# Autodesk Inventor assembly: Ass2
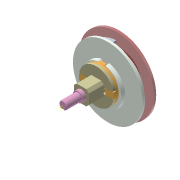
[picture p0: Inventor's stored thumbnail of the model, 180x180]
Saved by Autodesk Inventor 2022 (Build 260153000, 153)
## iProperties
Created: 2013-05
Part Number: Ass2
Document SubType Name: Assembly
Designer: hunter love
Author: hunter love
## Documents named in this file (7)
- C:\Users\x300\Desktop\compressore scroll\Ass2.iam
- C:\Users\x300\Desktop\compressore scroll\Base1.ipt
- C:\Users\x300\Desktop\compressore scroll\Wheel1.ipt
- C:\Users\x300\Desktop\compressore scroll\EccenShaft.ipt
- C:\Users\x300\Desktop\compressore scroll\DiskF.ipt
- C:\Users\x300\Desktop\compressore scroll\DiskM.ipt
- C:\Users\x300\Desktop\compressore scroll\AssDiskF.iam
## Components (6 placed, 6 different names)
1. Base1:3 — Mate:3, Mate:4, Mate:5, Mate:13, Angle:1, Angle:2, Angle:3, Mate:16
2. DiskF:1 — Mate:4, Mate:5, Mate:8, Mate:12, Angle:1
3. AssDiskF:1 [sub-assembly] — Mate:16, Mate:17
4. Wheel1:1 — Mate:11, Mate:17, Mate:20
5. DiskM:1 — Mate:8, Mate:11, Mate:12, Angle:3
6. EccenShaft:1 — Mate:3, Mate:13, Angle:2, Mate:20
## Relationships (13: Mate 10, Angle 3)
- Mate:3: Base1:3 ↔ EccenShaft:1
- Mate:4: Base1:3 ↔ DiskF:1
- Mate:5: Base1:3 ↔ DiskF:1
- Mate:8: DiskF:1 ↔ DiskM:1
- Mate:11: Wheel1:1 ↔ DiskM:1
- Mate:12: DiskF:1 ↔ DiskM:1
- Mate:13: Base1:3 ↔ EccenShaft:1
- Angle:1: Base1:3 ↔ DiskF:1
- Angle:2: Base1:3 ↔ EccenShaft:1
- Angle:3: Base1:3 ↔ DiskM:1
- Mate:16: Base1:3 ↔ AssDiskF:1
- Mate:17: AssDiskF:1 ↔ Wheel1:1
- Mate:20: Wheel1:1 ↔ EccenShaft:1
